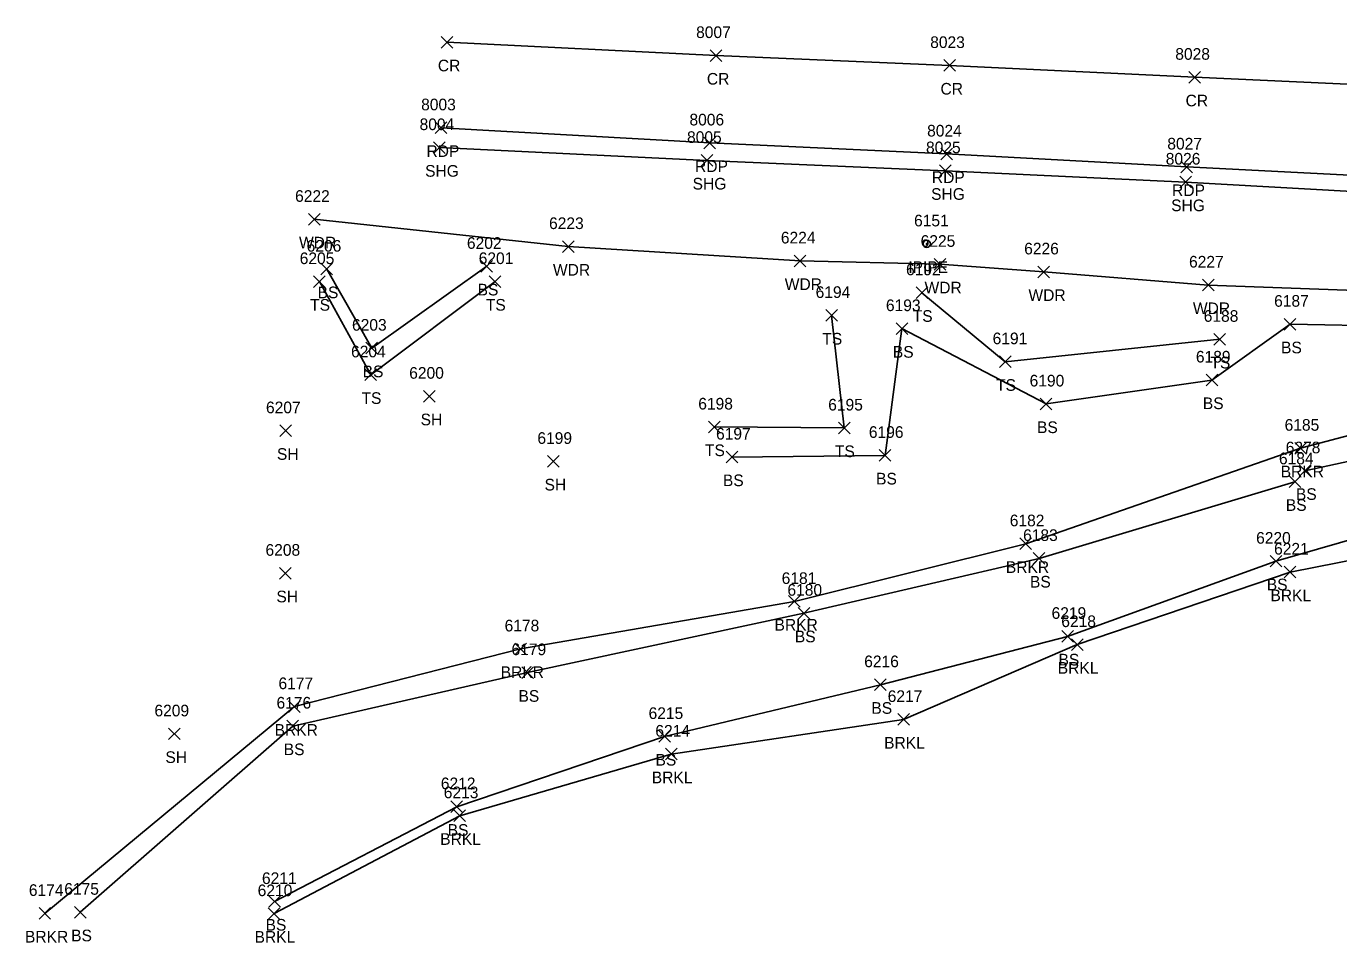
# Model space of a CAD drawing. Extents: x 1588028 to 1589597, y 137576 to 138176.
# Drawn here: x 1588348.7 to 1588574.1, y 137752.6 to 137909.9 of the extents above; entities that cross this region are included whole.
import ezdxf

# ---------------------------------------------------------------- set-up
doc = ezdxf.new("R2010")
doc.units = 0
for name, color, linetype in [('L_A', 7, 'Continuous'), ('L_I', 7, 'Continuous'), ('L_TIC', 7, 'Continuous'), ('LAWA', 7, 'Continuous'), ('LAWE', 7, 'Continuous'), ('LELB', 7, 'Continuous'), ('M_A', 7, 'Continuous'), ('M_I', 7, 'Continuous'), ('MPIP', 7, 'Continuous'), ('P_A', 7, 'Continuous'), ('P_I', 7, 'Continuous'), ('P_TIC', 7, 'Continuous'), ('PET', 7, 'Continuous'), ('PRC', 7, 'Continuous'), ('PSU', 7, 'Continuous')]:
    doc.layers.add(name, color=color, linetype=linetype)

msp = doc.modelspace()

# ---------------------------------------------------------------- linework, layer by layer
at = {"layer": 'L_TIC'}
for points in [[(1588397.21, 137875.79), (1588399.21, 137877.79)], [(1588399.21, 137875.79), (1588397.21, 137877.79)], [(1588440.82, 137871.12), (1588442.82, 137873.12)], [(1588442.82, 137871.12), (1588440.82, 137873.12)], [(1588480.62, 137868.65), (1588482.62, 137870.65)], [(1588482.62, 137868.65), (1588480.62, 137870.65)], [(1588399.33, 137867.24), (1588401.33, 137869.24)], [(1588401.33, 137867.24), (1588399.33, 137869.24)], [(1588426.8, 137867.72), (1588428.8, 137869.72)], [(1588428.8, 137867.72), (1588426.8, 137869.72)], [(1588504.62, 137868.07), (1588506.62, 137870.07)], [(1588506.62, 137868.07), (1588504.62, 137870.07)], [(1588522.45, 137866.77), (1588524.45, 137868.77)], [(1588524.45, 137866.77), (1588522.45, 137868.77)], [(1588398.08, 137865.1), (1588400.08, 137867.1)], [(1588400.08, 137865.1), (1588398.08, 137867.1)], [(1588428.25, 137865.11), (1588430.25, 137867.11)], [(1588430.25, 137865.11), (1588428.25, 137867.11)], [(1588550.7, 137864.51), (1588552.7, 137866.51)], [(1588552.7, 137864.51), (1588550.7, 137866.51)], [(1588501.54, 137863.19), (1588503.54, 137865.19)], [(1588503.54, 137863.19), (1588501.54, 137865.19)], [(1588486.02, 137859.29), (1588488.02, 137861.29)], [(1588488.02, 137859.29), (1588486.02, 137861.29)], [(1588564.74, 137857.78), (1588566.74, 137859.78)], [(1588566.74, 137857.78), (1588564.74, 137859.78)], [(1588498.09, 137857.03), (1588500.09, 137859.03)], [(1588500.09, 137857.03), (1588498.09, 137859.03)], [(1588552.66, 137855.19), (1588554.66, 137857.19)], [(1588554.66, 137855.19), (1588552.66, 137857.19)], [(1588407.06, 137853.67), (1588409.06, 137855.67)], [(1588409.06, 137853.67), (1588407.06, 137855.67)], [(1588515.85, 137851.34), (1588517.85, 137853.34)], [(1588517.85, 137851.34), (1588515.85, 137853.34)], [(1588406.9, 137849.09), (1588408.9, 137851.09)], [(1588408.9, 137849.09), (1588406.9, 137851.09)], [(1588551.32, 137848.2), (1588553.32, 137850.2)], [(1588553.32, 137848.2), (1588551.32, 137850.2)], [(1588416.97, 137845.42), (1588418.97, 137847.42)], [(1588418.97, 137845.42), (1588416.97, 137847.42)], [(1588522.84, 137844.09), (1588524.84, 137846.09)], [(1588524.84, 137844.09), (1588522.84, 137846.09)], [(1588392.3, 137839.49), (1588394.3, 137841.49)], [(1588394.3, 137839.49), (1588392.3, 137841.49)], [(1588465.87, 137840.13), (1588467.87, 137842.13)], [(1588467.87, 137840.13), (1588465.87, 137842.13)], [(1588488.19, 137839.96), (1588490.19, 137841.96)], [(1588490.19, 137839.96), (1588488.19, 137841.96)], [(1588468.92, 137834.97), (1588470.92, 137836.97)], [(1588470.92, 137834.97), (1588468.92, 137836.97)], [(1588495.21, 137835.26), (1588497.21, 137837.26)], [(1588497.21, 137835.26), (1588495.21, 137837.26)], [(1588566.54, 137836.49), (1588568.54, 137838.49)], [(1588568.54, 137836.49), (1588566.54, 137838.49)], [(1588438.25, 137834.23), (1588440.25, 137836.23)], [(1588440.25, 137834.23), (1588438.25, 137836.23)], [(1588567.3, 137832.61), (1588569.3, 137834.61)], [(1588569.3, 137832.61), (1588567.3, 137834.61)], [(1588565.57, 137830.73), (1588567.57, 137832.73)], [(1588567.57, 137830.73), (1588565.57, 137832.73)], [(1588519.35, 137820.08), (1588521.35, 137822.08)], [(1588521.35, 137820.08), (1588519.35, 137822.08)], [(1588521.64, 137817.56), (1588523.64, 137819.56)], [(1588523.64, 137817.56), (1588521.64, 137819.56)], [(1588562.3, 137817.09), (1588564.3, 137819.09)], [(1588564.3, 137817.09), (1588562.3, 137819.09)], [(1588392.21, 137815.02), (1588394.21, 137817.02)], [(1588394.21, 137815.02), (1588392.21, 137817.02)], [(1588564.73, 137815.22), (1588566.73, 137817.22)], [(1588566.73, 137815.22), (1588564.73, 137817.22)], [(1588479.63, 137810.17), (1588481.63, 137812.17)], [(1588481.63, 137810.17), (1588479.63, 137812.17)], [(1588481.27, 137808.16), (1588483.27, 137810.16)], [(1588483.27, 137808.16), (1588481.27, 137810.16)], [(1588526.54, 137804.18), (1588528.54, 137806.18)], [(1588528.54, 137804.18), (1588526.54, 137806.18)], [(1588432.62, 137802.03), (1588434.62, 137804.03)], [(1588434.62, 137802.03), (1588432.62, 137804.03)], [(1588528.2, 137802.77), (1588530.2, 137804.77)], [(1588530.2, 137802.77), (1588528.2, 137804.77)], [(1588433.82, 137797.95), (1588435.82, 137799.95)], [(1588435.82, 137797.95), (1588433.82, 137799.95)], [(1588494.41, 137795.88), (1588496.41, 137797.88)], [(1588496.41, 137795.88), (1588494.41, 137797.88)], [(1588393.8, 137792.11), (1588395.8, 137794.11)], [(1588395.8, 137792.11), (1588393.8, 137794.11)], [(1588498.39, 137789.91), (1588500.39, 137791.91)], [(1588500.39, 137789.91), (1588498.39, 137791.91)], [(1588393.51, 137788.78), (1588395.51, 137790.78)], [(1588395.51, 137788.78), (1588393.51, 137790.78)], [(1588373.15, 137787.44), (1588375.15, 137789.44)], [(1588375.15, 137787.44), (1588373.15, 137789.44)], [(1588457.34, 137786.99), (1588459.34, 137788.99)], [(1588459.34, 137786.99), (1588457.34, 137788.99)], [(1588458.5, 137783.96), (1588460.5, 137785.96)], [(1588460.5, 137783.96), (1588458.5, 137785.96)], [(1588421.67, 137774.93), (1588423.67, 137776.93)], [(1588423.67, 137774.93), (1588421.67, 137776.93)], [(1588422.17, 137773.38), (1588424.17, 137775.38)], [(1588424.17, 137773.38), (1588422.17, 137775.38)], [(1588390.4, 137758.65), (1588392.4, 137760.65)], [(1588392.4, 137758.65), (1588390.4, 137760.65)], [(1588350.94, 137756.61), (1588352.94, 137758.61)], [(1588352.94, 137756.61), (1588350.94, 137758.61)], [(1588357.02, 137756.81), (1588359.02, 137758.81)], [(1588359.02, 137756.81), (1588357.02, 137758.81)], [(1588390.31, 137756.57), (1588392.31, 137758.57)], [(1588392.31, 137756.57), (1588390.31, 137758.57)]]:
    msp.add_lwpolyline(points, dxfattribs=at)
at = {"layer": 'LAWA'}
msp.add_lwpolyline([(1588398.21, 137876.79), (1588441.82, 137872.12), (1588481.62, 137869.65), (1588505.62, 137869.07), (1588523.45, 137867.77), (1588551.7, 137865.51), (1588580.18, 137864.47), (1588606.62, 137862.97), (1588631.95, 137855.73), (1588631.68, 137848.28)], dxfattribs=at)
at = {"layer": 'LAWE'}
for points in [[(1588351.94, 137757.61), (1588394.8, 137793.11), (1588433.62, 137803.03), (1588480.63, 137811.17), (1588520.35, 137821.08), (1588567.54, 137837.49), (1588589.88, 137843.37), (1588617.9, 137843.15), (1588641.92, 137842.86), (1588676.03, 137841.63), (1588690.85, 137840.73)], [(1588391.31, 137757.57), (1588423.17, 137774.38), (1588459.5, 137784.96), (1588499.39, 137790.91), (1588529.2, 137803.77), (1588565.73, 137816.22), (1588590.41, 137821.05), (1588622.01, 137824.55), (1588648.03, 137824.83), (1588677.48, 137821.62), (1588692.6, 137825.72)]]:
    msp.add_lwpolyline(points, dxfattribs=at)
at = {"layer": 'LELB'}
for points in [[(1588427.8, 137868.72), (1588408.06, 137854.67), (1588400.33, 137868.24)], [(1588429.25, 137866.11), (1588407.9, 137850.09), (1588399.08, 137866.1)], [(1588553.66, 137856.19), (1588516.85, 137852.34), (1588502.54, 137864.19)], [(1588487.02, 137860.29), (1588489.19, 137840.96), (1588466.87, 137841.13)], [(1588601.33, 137858.09), (1588565.74, 137858.78), (1588552.32, 137849.2), (1588523.84, 137845.09), (1588499.09, 137858.03), (1588496.21, 137836.26), (1588469.92, 137835.97)], [(1588391.4, 137759.65), (1588422.67, 137775.93), (1588458.34, 137787.99), (1588495.41, 137796.88), (1588527.54, 137805.18), (1588563.3, 137818.09), (1588592.33, 137826.45), (1588623.21, 137828.91), (1588648.72, 137826.34), (1588676.42, 137824.29), (1588692.66, 137827.33), (1588691, 137838.01), (1588661.91, 137839.36), (1588634.48, 137841.03), (1588600.38, 137840.56), (1588568.3, 137833.61)], [(1588358.02, 137757.81), (1588394.51, 137789.78), (1588434.82, 137798.95), (1588482.27, 137809.16), (1588522.64, 137818.56), (1588566.57, 137831.73)]]:
    msp.add_lwpolyline(points, dxfattribs=at)
at = {"layer": 'MPIP'}
for radius in [0.625, 0.0833]:
    msp.add_circle((1588503.35, 137872.58), radius, dxfattribs=at)
at = {"layer": 'P_TIC'}
for points in [[(1588419.99, 137906.2), (1588421.99, 137908.2)], [(1588421.99, 137906.2), (1588419.99, 137908.2)], [(1588466.18, 137903.92), (1588468.18, 137905.92)], [(1588468.18, 137903.92), (1588466.18, 137905.92)], [(1588506.29, 137902.21), (1588508.29, 137904.21)], [(1588508.29, 137902.21), (1588506.29, 137904.21)], [(1588548.37, 137900.19), (1588550.37, 137902.19)], [(1588550.37, 137900.19), (1588548.37, 137902.19)], [(1588418.97, 137891.51), (1588420.97, 137893.51)], [(1588420.97, 137891.51), (1588418.97, 137893.51)], [(1588418.69, 137888.11), (1588420.69, 137890.11)], [(1588420.69, 137888.11), (1588418.69, 137890.11)], [(1588465.09, 137888.91), (1588467.09, 137890.91)], [(1588467.09, 137888.91), (1588465.09, 137890.91)], [(1588505.76, 137887.01), (1588507.76, 137889.01)], [(1588507.76, 137887.01), (1588505.76, 137889.01)], [(1588464.62, 137885.91), (1588466.62, 137887.91)], [(1588466.62, 137885.91), (1588464.62, 137887.91)], [(1588547, 137884.78), (1588549, 137886.78)], [(1588549, 137884.78), (1588547, 137886.78)], [(1588505.57, 137884.14), (1588507.57, 137886.14)], [(1588507.57, 137884.14), (1588505.57, 137886.14)], [(1588546.79, 137882.19), (1588548.79, 137884.19)], [(1588548.79, 137882.19), (1588546.79, 137884.19)]]:
    msp.add_lwpolyline(points, dxfattribs=at)
at = {"layer": 'PET'}
msp.add_lwpolyline([(1588419.97, 137892.51), (1588466.09, 137889.91), (1588506.76, 137888.01), (1588548, 137885.78), (1588590.45, 137883.61), (1588638.45, 137880.69), (1588661.69, 137879.38), (1588677.51, 137878.09), (1588721.13, 137874.78), (1588740.19, 137872.99), (1588782.63, 137867.93), (1588820.21, 137862.87), (1588860.26, 137857.26), (1588914.01, 137849.9), (1588927.99, 137847.51)], dxfattribs=at)
at = {"layer": 'PRC'}
msp.add_lwpolyline([(1588420.99, 137907.2), (1588467.18, 137904.92), (1588507.29, 137903.21), (1588549.37, 137901.19), (1588590.55, 137899.3), (1588641.57, 137896.1), (1588661.53, 137894.88), (1588702.39, 137891.26), (1588744.44, 137887.15), (1588784.4, 137882.3), (1588823.71, 137877.3), (1588862.06, 137871.74), (1588917.24, 137863.85)], dxfattribs=at)
at = {"layer": 'PSU'}
msp.add_lwpolyline([(1588419.69, 137889.11), (1588465.62, 137886.91), (1588506.57, 137885.14), (1588547.79, 137883.19), (1588590.68, 137880.74), (1588637.76, 137877.66), (1588661.23, 137875.7), (1588680.63, 137875.71)], dxfattribs=at)

# ---------------------------------------------------------------- texts
at = {"layer": 'L_A'}
for s, p in [('WDR', (1588395.58, 137871.79)), ('WDR', (1588439.18, 137867.12)), ('WDR', (1588478.98, 137864.65)), ('BS', (1588398.77, 137863.24)), ('BS', (1588426.24, 137863.72)), ('WDR', (1588502.98, 137864.07)), ('WDR', (1588520.82, 137862.77)), ('TS', (1588397.49, 137861.1)), ('TS', (1588427.66, 137861.11)), ('WDR', (1588549.06, 137860.51)), ('TS', (1588500.95, 137859.19)), ('TS', (1588485.43, 137855.29)), ('BS', (1588497.54, 137853.03)), ('BS', (1588564.19, 137853.78)), ('TS', (1588552.06, 137851.19)), ('BS', (1588406.51, 137849.67)), ('TS', (1588515.26, 137847.34)), ('TS', (1588406.31, 137845.09)), ('BS', (1588550.76, 137844.2)), ('SH', (1588416.46, 137841.42)), ('BS', (1588522.29, 137840.09)), ('SH', (1588391.79, 137835.49)), ('TS', (1588465.28, 137836.13)), ('TS', (1588487.59, 137835.96)), ('BS', (1588468.36, 137830.97)), ('BS', (1588494.66, 137831.26)), ('BRKR', (1588564.13, 137832.49)), ('SH', (1588437.74, 137830.23)), ('BS', (1588566.74, 137828.61)), ('BS', (1588565.01, 137826.73)), ('BRKR', (1588516.94, 137816.08)), ('BS', (1588521.08, 137813.56)), ('BS', (1588561.74, 137813.09)), ('SH', (1588391.7, 137811.02)), ('BRKL', (1588562.37, 137811.22)), ('BRKR', (1588477.22, 137806.17)), ('BS', (1588480.71, 137804.16)), ('BRKL', (1588525.85, 137798.77)), ('BS', (1588525.98, 137800.18)), ('BRKR', (1588430.21, 137798.03)), ('BS', (1588433.26, 137793.95)), ('BS', (1588493.85, 137791.88)), ('BRKR', (1588391.39, 137788.11)), ('BRKL', (1588496.04, 137785.91)), ('SH', (1588372.64, 137783.44)), ('BS', (1588392.96, 137784.78)), ('BS', (1588456.79, 137782.99)), ('BRKL', (1588456.15, 137779.96)), ('BS', (1588421.11, 137770.93)), ('BRKL', (1588419.82, 137769.38)), ('BS', (1588389.84, 137754.65)), ('BRKR', (1588348.53, 137752.61)), ('BS', (1588356.46, 137752.81)), ('BRKL', (1588387.95, 137752.57))]:
    msp.add_text(s, height=2, dxfattribs=at).set_placement(p)
at = {"layer": 'L_I'}
for s, p in [('6222', (1588394.91, 137879.79)), ('6223', (1588438.51, 137875.12)), ('6206', (1588396.89, 137871.24)), ('6202', (1588424.41, 137871.72)), ('6224', (1588478.31, 137872.65)), ('6225', (1588502.31, 137872.07)), ('6205', (1588395.7, 137869.1)), ('6201', (1588426.43, 137869.11)), ('6226', (1588520.09, 137870.77)), ('6192', (1588499.8, 137867.19)), ('6227', (1588548.39, 137868.51)), ('6194', (1588484.28, 137863.29)), ('6193', (1588496.35, 137861.03)), ('6187', (1588563, 137861.78)), ('6203', (1588404.68, 137857.67)), ('6188', (1588550.91, 137859.19)), ('6191', (1588514.67, 137855.34)), ('6204', (1588404.52, 137853.09)), ('6189', (1588549.57, 137852.2)), ('6200', (1588414.5, 137849.42)), ('6190', (1588521.02, 137848.09)), ('6198', (1588464.13, 137844.13)), ('6195', (1588486.44, 137843.96)), ('6207', (1588389.91, 137843.49)), ('6185', (1588564.8, 137840.49)), ('6199', (1588436.51, 137838.23)), ('6197', (1588467.18, 137838.97)), ('6196', (1588493.42, 137839.26)), ('6278', (1588564.99, 137836.61)), ('6184', (1588563.83, 137834.73)), ('6182', (1588517.61, 137824.08)), ('6183', (1588519.9, 137821.56)), ('6220', (1588559.91, 137821.09)), ('6221', (1588562.99, 137819.22)), ('6208', (1588389.83, 137819.02)), ('6181', (1588478.45, 137814.17)), ('6180', (1588479.44, 137812.16)), ('6219', (1588524.79, 137808.18)), ('6178', (1588430.88, 137806.03)), ('6218', (1588526.46, 137806.77)), ('6179', (1588432.07, 137801.95)), ('6216', (1588492.62, 137799.88)), ('6177', (1588392.06, 137796.11)), ('6176', (1588391.72, 137792.78)), ('6217', (1588496.65, 137793.91)), ('6209', (1588370.76, 137791.44)), ('6215', (1588455.6, 137790.99)), ('6214', (1588456.76, 137787.96)), ('6212', (1588419.93, 137778.93)), ('6213', (1588420.43, 137777.38)), ('6174', (1588349.2, 137760.61)), ('6175', (1588355.28, 137760.81)), ('6210', (1588388.48, 137760.57)), ('6211', (1588389.22, 137762.65))]:
    msp.add_text(s, height=2, dxfattribs=at).set_placement(p)
at = {"layer": 'M_A'}
msp.add_text('IPIPE', height=2, dxfattribs=at).set_placement((1588500.19, 137867.58))
at = {"layer": 'M_I'}
msp.add_text('6151', height=2, dxfattribs=at).set_placement((1588501.18, 137875.58))
at = {"layer": 'P_A'}
for s, p in [('CR', (1588419.42, 137902.2)), ('CR', (1588465.61, 137899.92)), ('CR', (1588505.72, 137898.21)), ('CR', (1588547.8, 137896.19)), ('RDP', (1588417.46, 137887.51)), ('RDP', (1588463.58, 137884.91)), ('SHG', (1588417.23, 137884.11)), ('RDP', (1588504.24, 137883.01)), ('SHG', (1588463.16, 137881.91)), ('SHG', (1588504.11, 137880.14)), ('RDP', (1588545.48, 137880.78)), ('SHG', (1588545.32, 137878.19))]:
    msp.add_text(s, height=2, dxfattribs=at).set_placement(p)
at = {"layer": 'P_I'}
for s, p in [('8007', (1588463.76, 137907.92)), ('8023', (1588503.95, 137906.21)), ('8028', (1588546.03, 137904.19)), ('8003', (1588416.55, 137895.51)), ('8004', (1588416.28, 137892.11)), ('8006', (1588462.62, 137892.91)), ('8005', (1588462.2, 137889.91)), ('8024', (1588503.42, 137891.01)), ('8025', (1588503.23, 137888.14)), ('8027', (1588544.66, 137888.78)), ('8026', (1588544.39, 137886.19))]:
    msp.add_text(s, height=2, dxfattribs=at).set_placement(p)

doc.saveas('drawing.dxf')
